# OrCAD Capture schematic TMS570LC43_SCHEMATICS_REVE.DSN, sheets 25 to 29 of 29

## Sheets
25 PAGE15: FET SWs FOR 2nd USB: size B; note: FET SWs FOR USB DEVICE & 2nd HOST
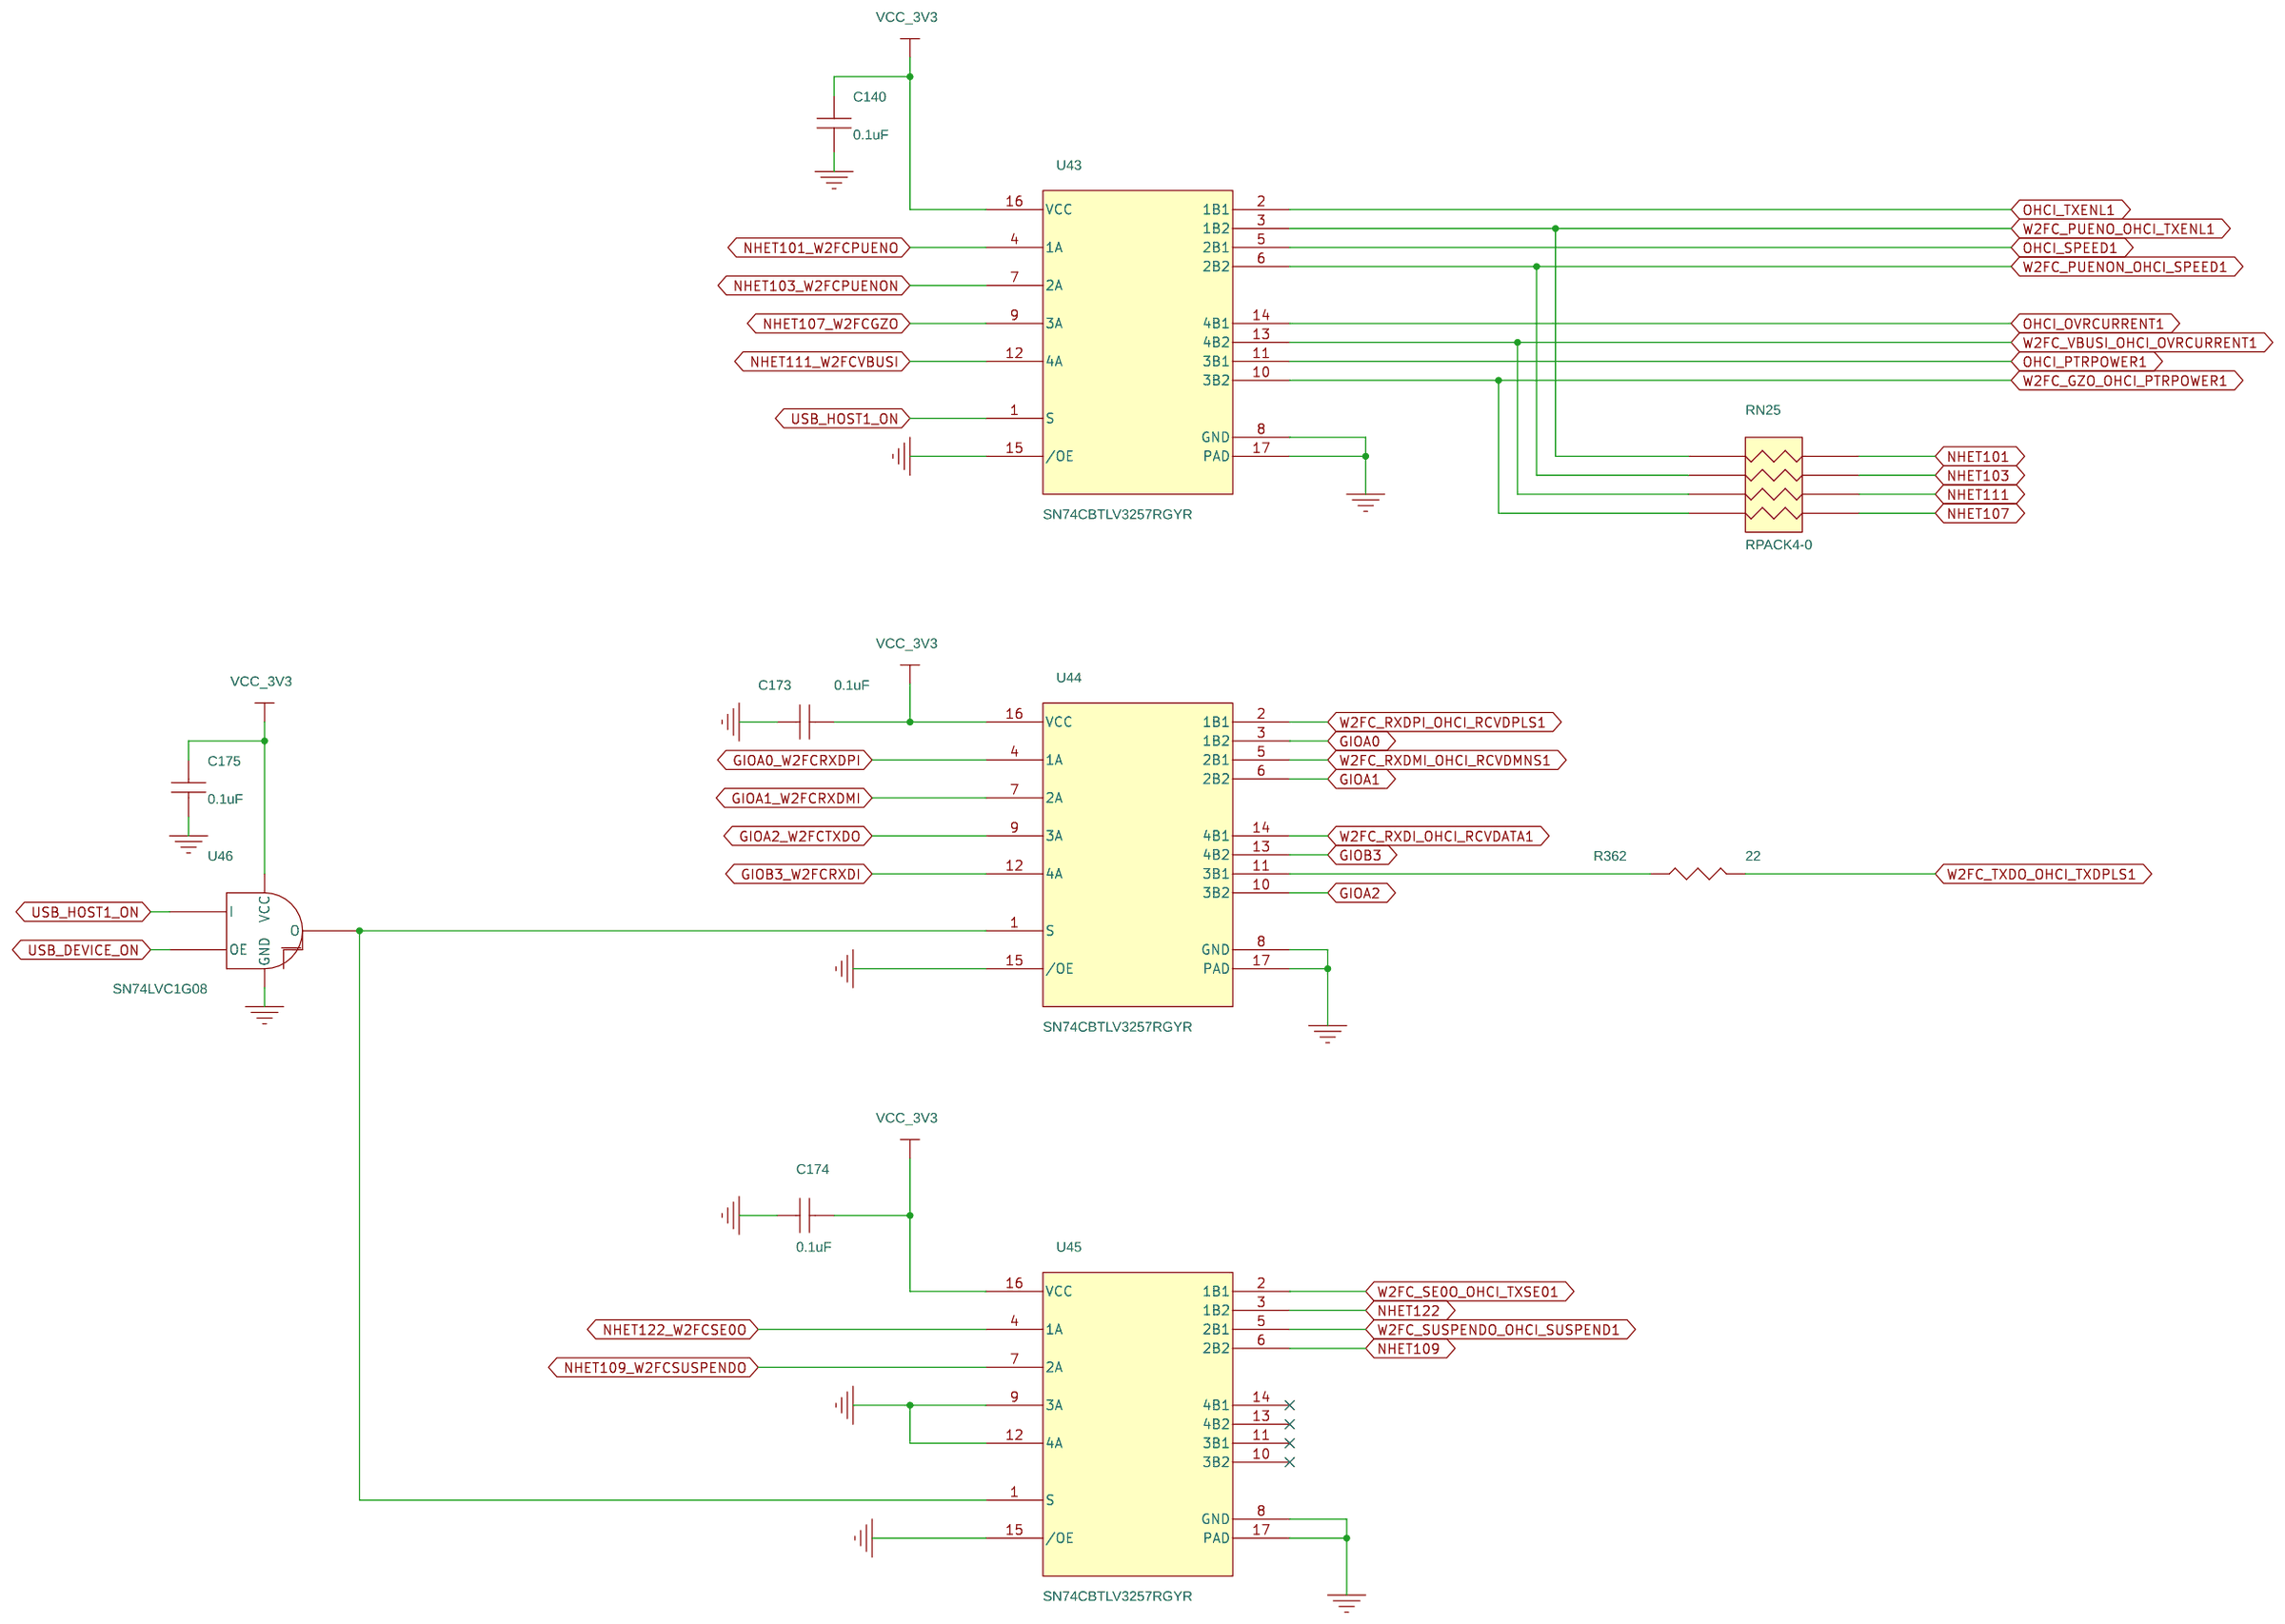
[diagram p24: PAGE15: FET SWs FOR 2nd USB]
26 PAGE06: MCU DCAN, FRAY, LIN: size B; rev: D; note: MCU DCAN, FRAY, LIN
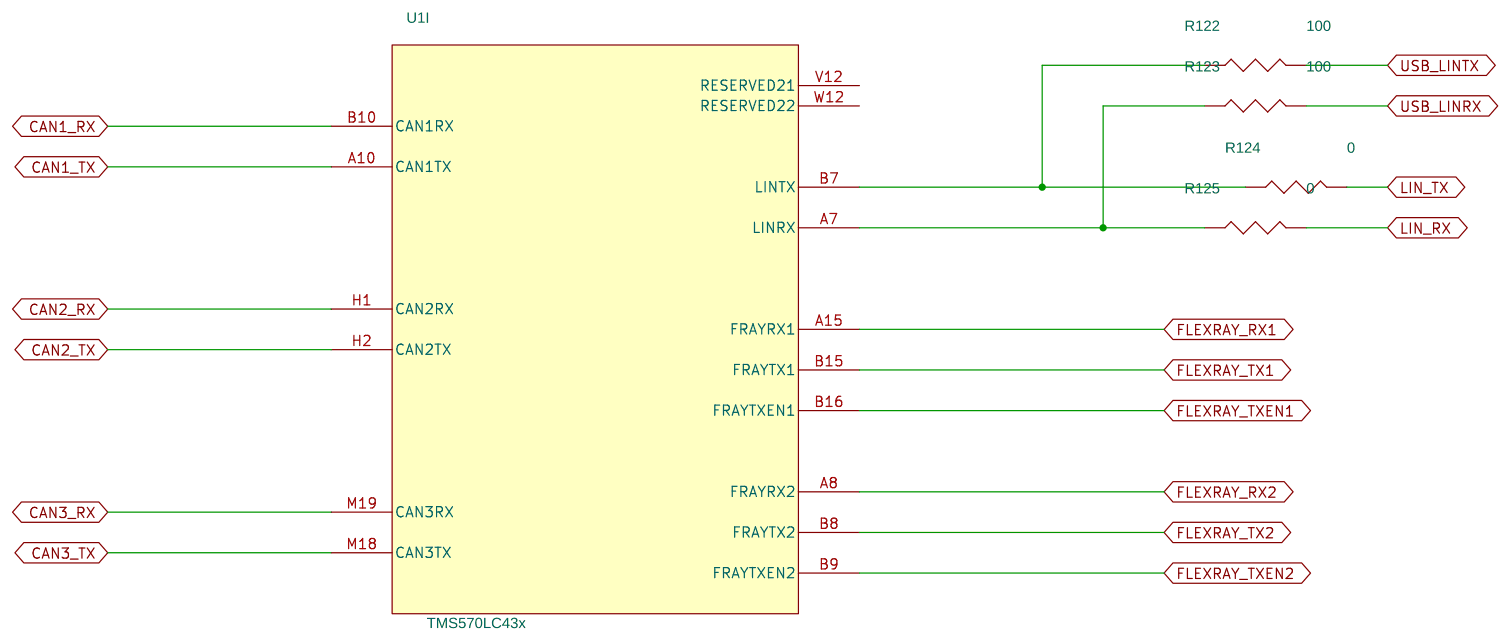
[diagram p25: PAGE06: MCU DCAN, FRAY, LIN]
27 PAGE17: USB Device & 2nd HOST: size B; note: USB Device & 2nd HOST
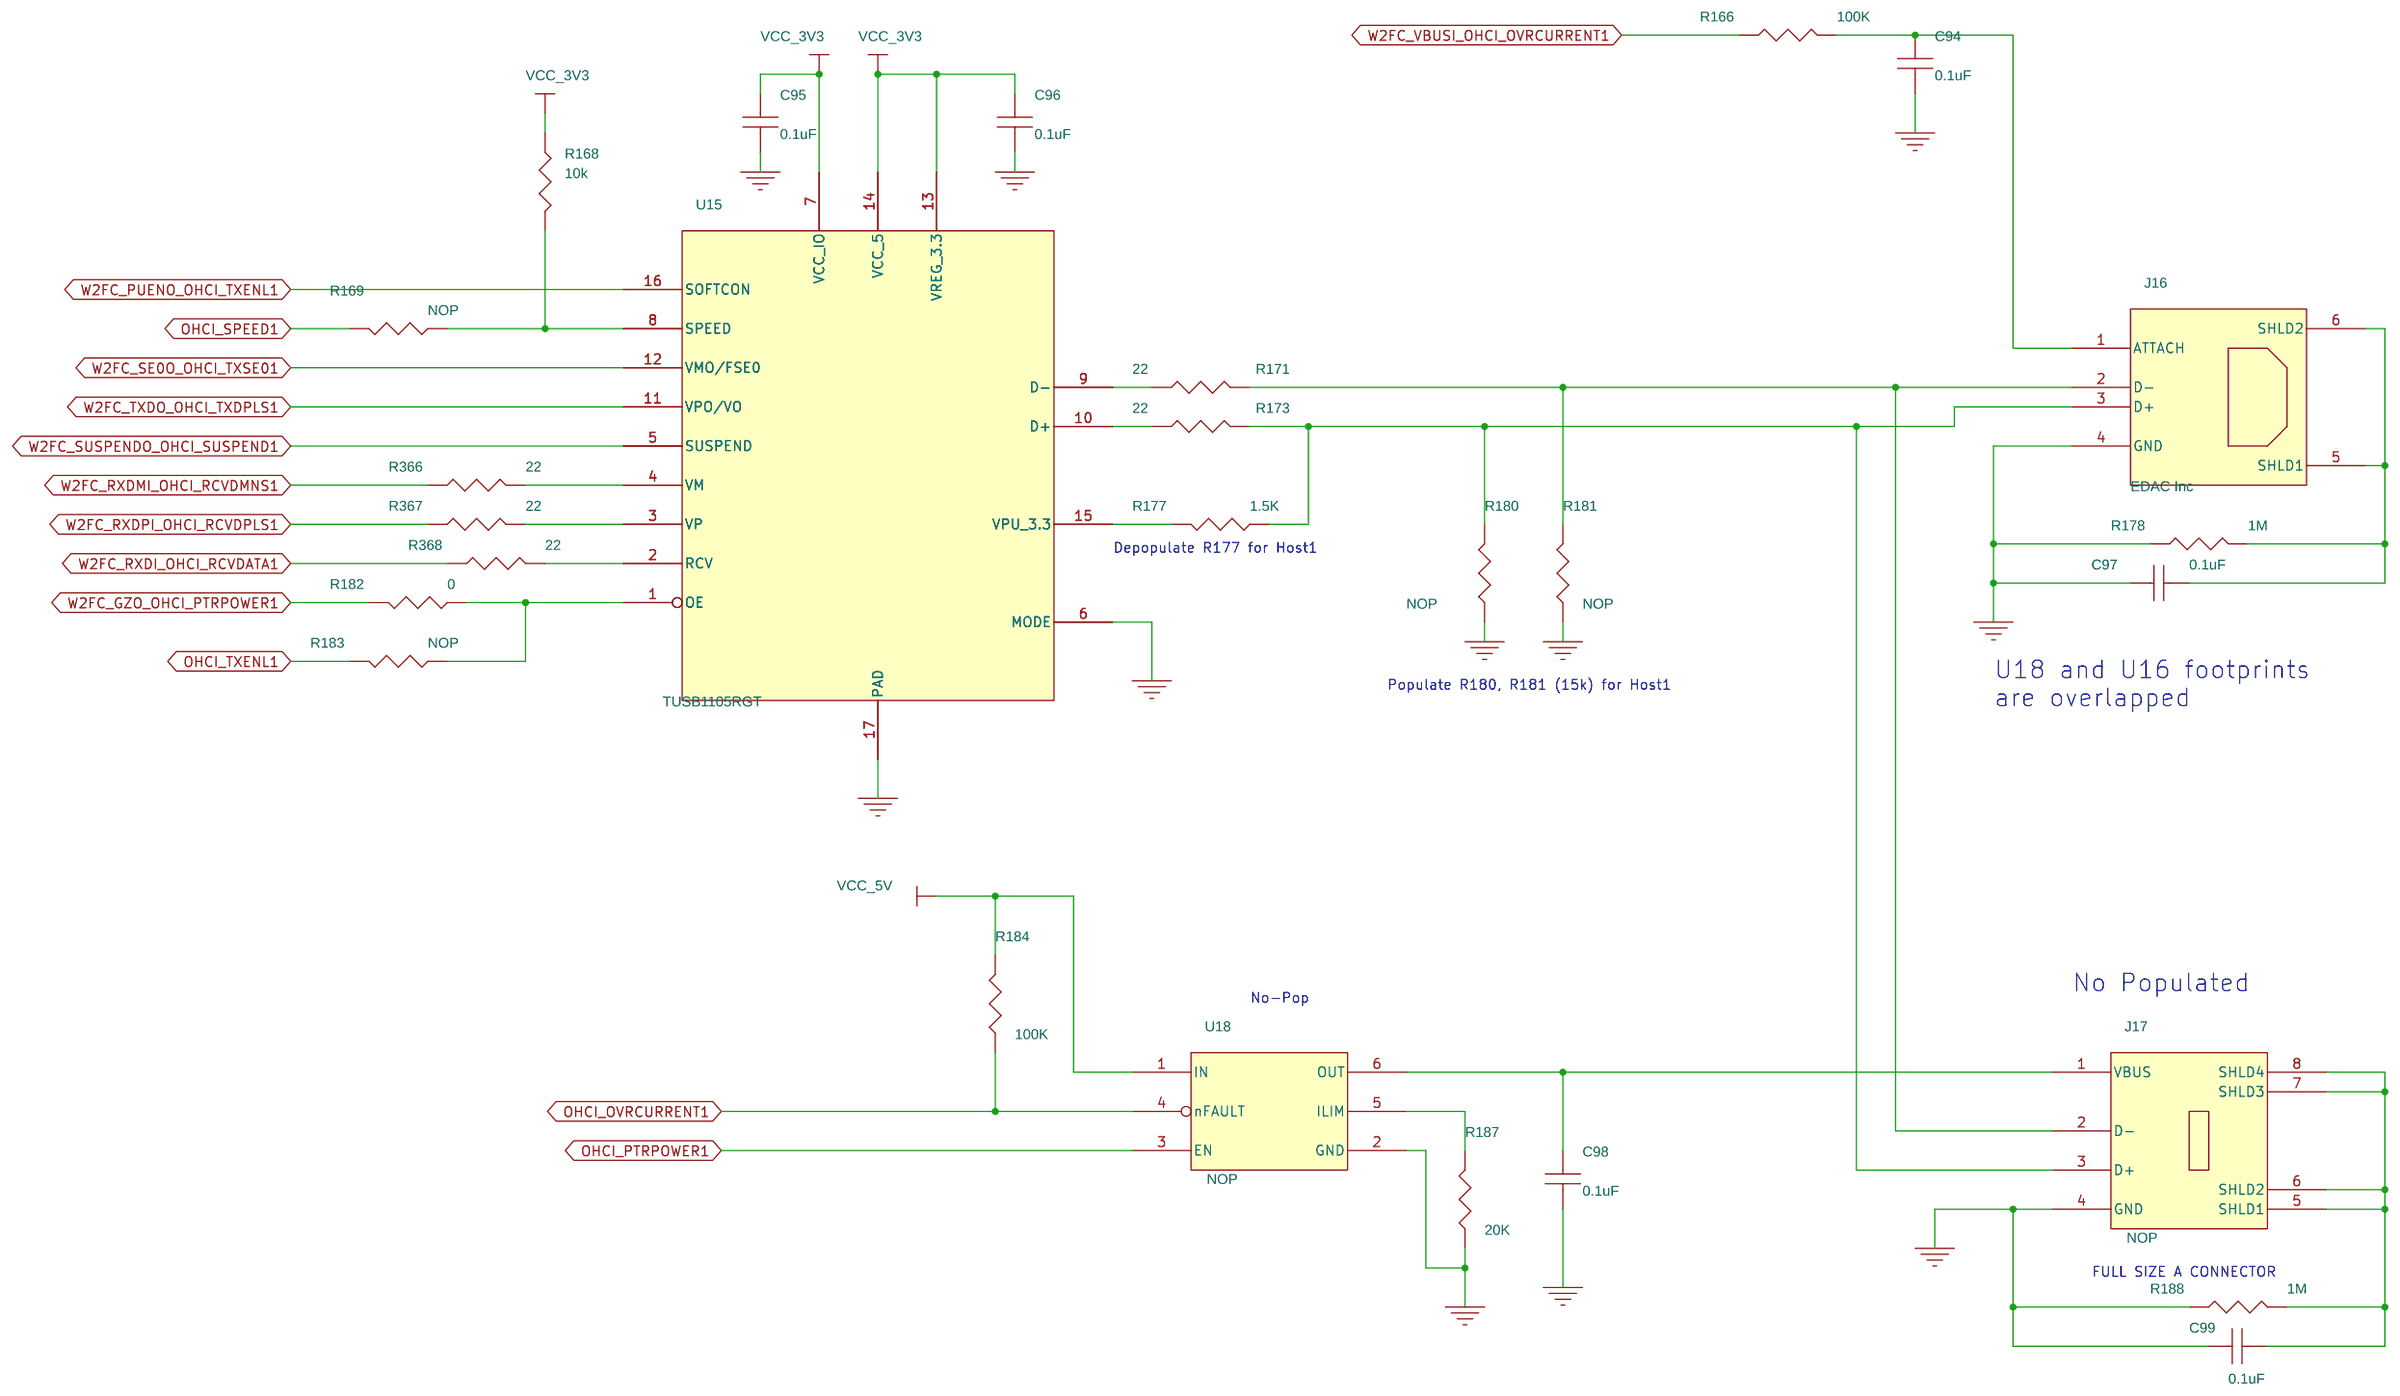
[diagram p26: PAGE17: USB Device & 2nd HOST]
28 PAGE19: Ethernet PHY & Conn: size B; note: Ethernet PHY & Conn
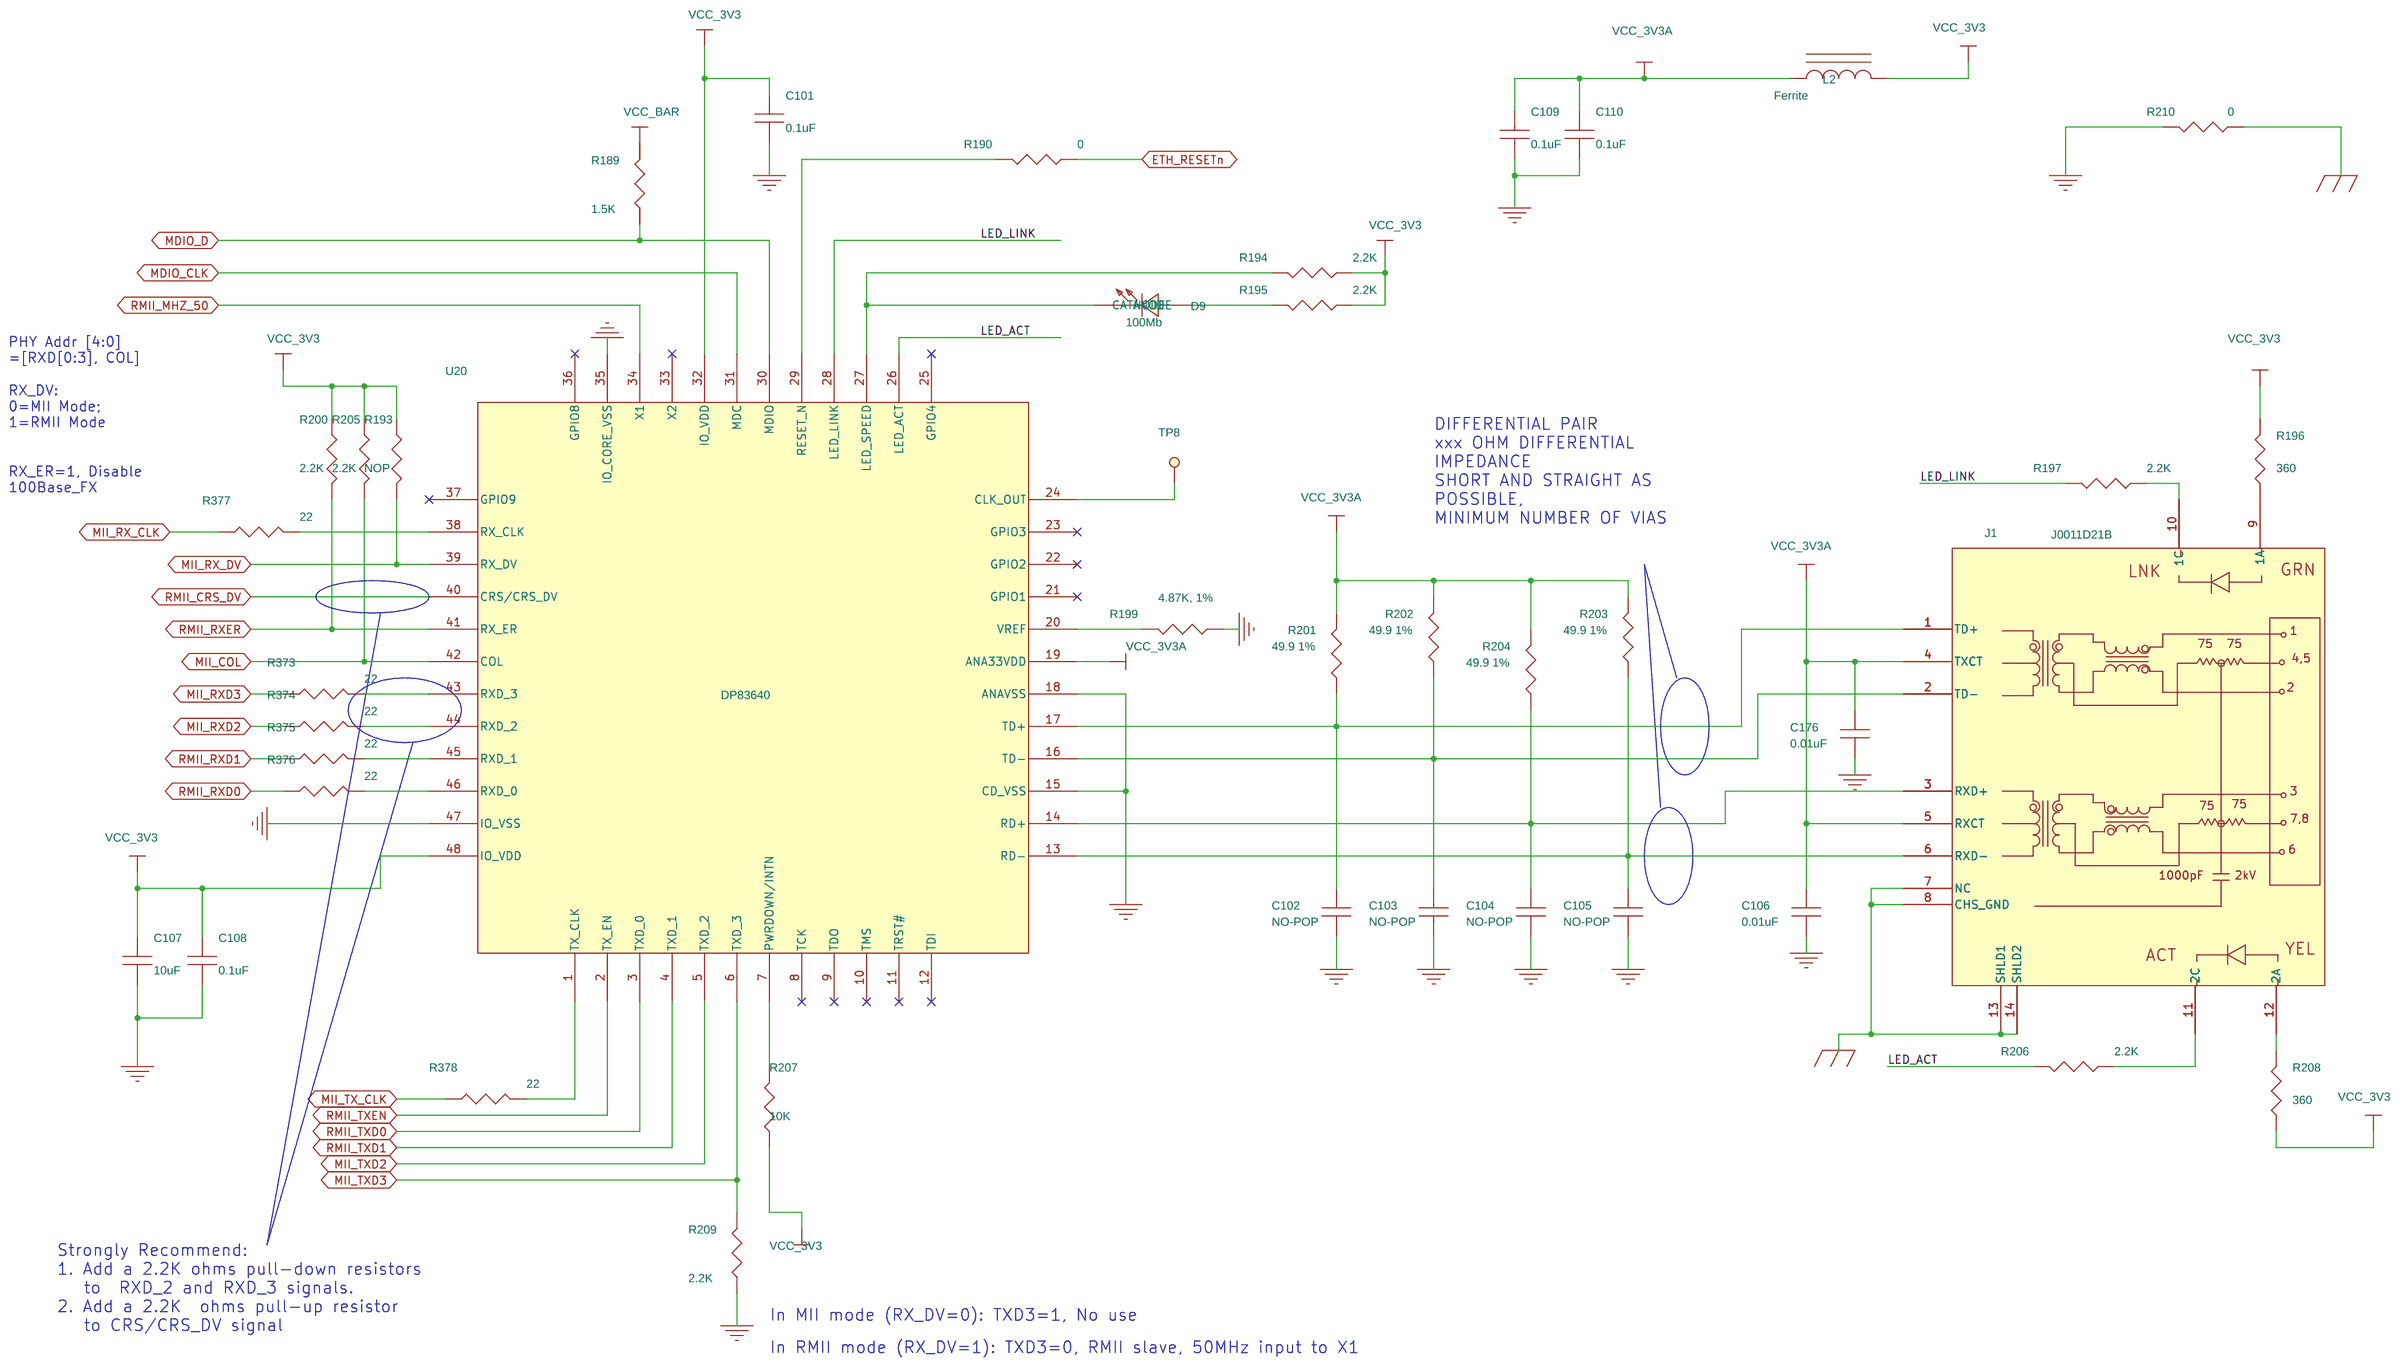
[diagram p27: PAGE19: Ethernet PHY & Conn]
29 PAGE18: FET SW 4 RMII & DIP SW: size B; note: FET SW 4 RMII & DIP SW
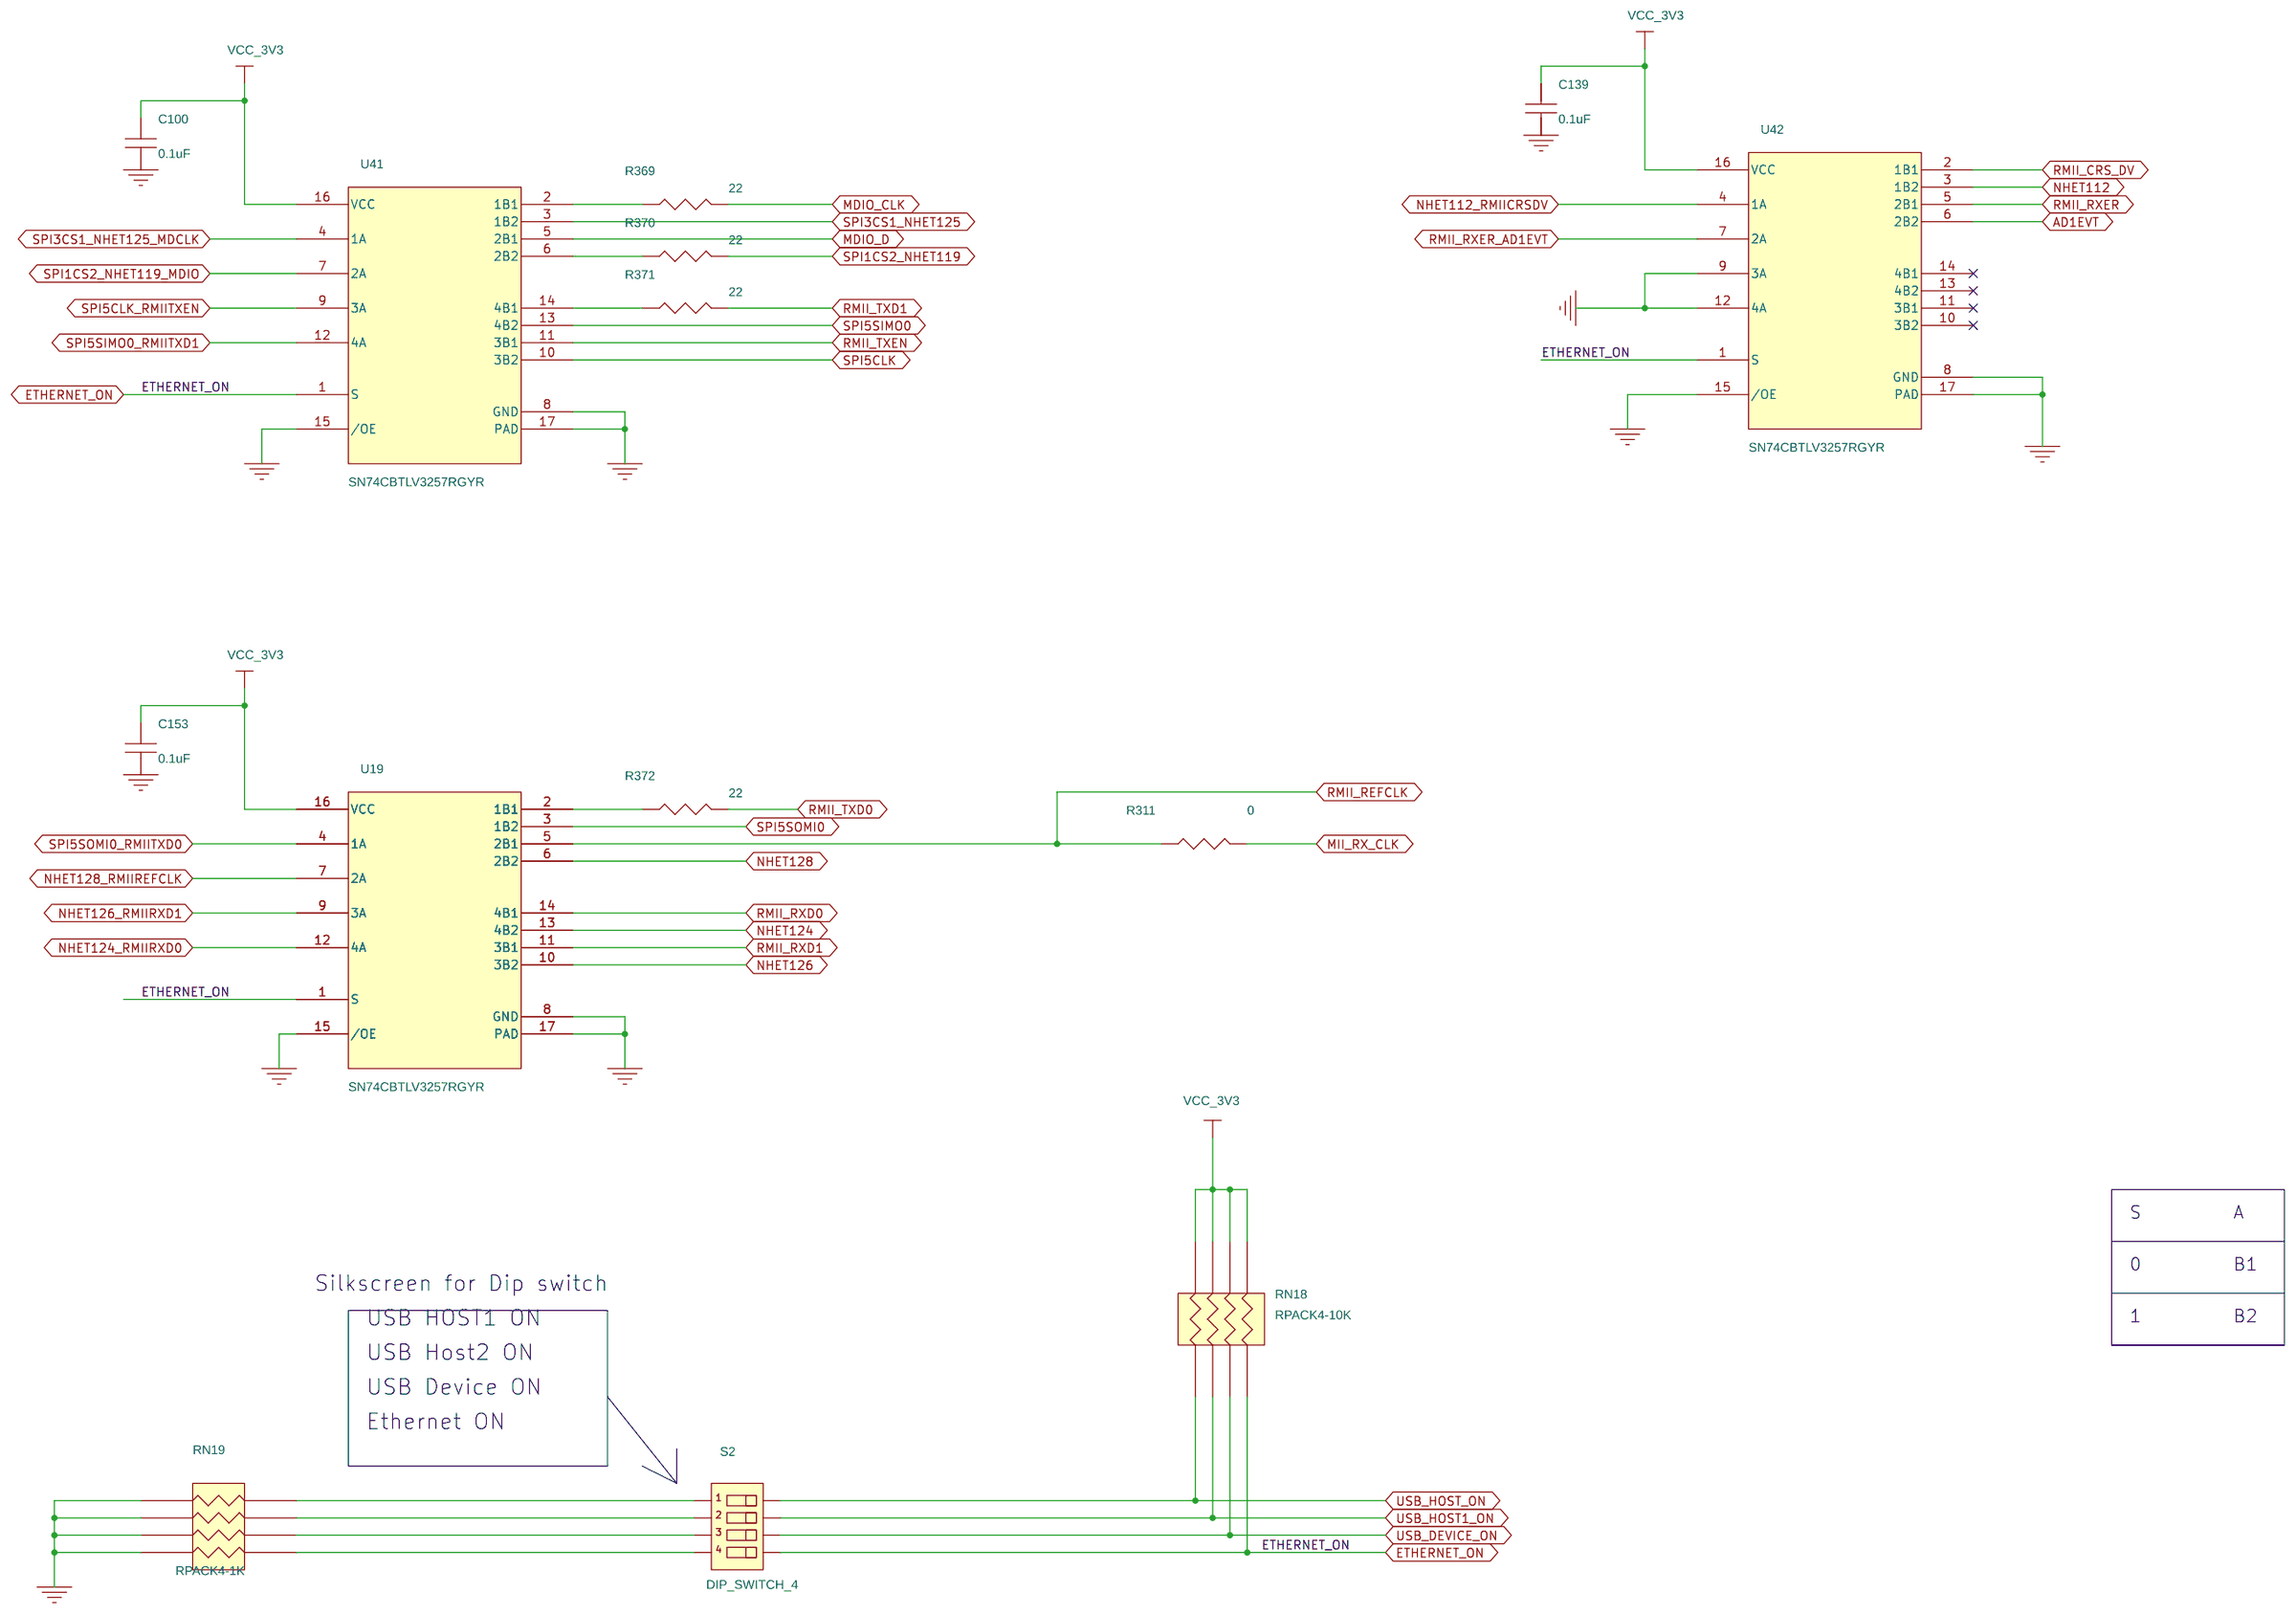
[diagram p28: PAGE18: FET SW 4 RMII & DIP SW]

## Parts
sheet PAGE05: MCU ETM & RSVED_RTP
U1  TMS570LC43x  [BGA337]  (sections A,B,C,D,E,F,G,H,I)
sheet PAGE06: MCU DCAN, FRAY, LIN
R122  100  [r0402]
R123  100  [r0402]
R124  0  [r0402]
R125  0  [r0402]
sheet PAGE15: FET SWs FOR 2nd USB
C140  0.1uF  [c0402]
C173  0.1uF  [c0402]
C174  0.1uF  [c0402]
C175  0.1uF  [c0402]
R362  22  [r0402]
RN25  RPACK4-0  [EXB-28VS]
U43  SN74CBTLV3257RGYR  [VQFN16]
U44  SN74CBTLV3257RGYR  [VQFN16]
U45  SN74CBTLV3257RGYR  [VQFN16]
U46  SN74LVC1G08  [SOT-553]
sheet PAGE17: USB Device & 2nd HOST
C94  0.1uF  [c0402]
C95  0.1uF  [c0402]
C96  0.1uF  [c0402]
C97  0.1uF  [c0402]
C98  0.1uF  [c0402]
C99  0.1uF  [c0402]
J16  EDAC Inc  [USB-B]
J17  NOP  [USB-A]
R166  100K  [r0402]
R168  10k  [r0402]
R169  NOP  [r0402]
R171  22  [r0402]
R173  22  [r0402]
R177  1.5K  [r0402]
R178  1M  [r0402]
R180  NOP  [r0402]
R181  NOP  [r0402]
R182  0  [r0402]
R183  NOP  [r0402]
R184  100K  [r0402]
R187  20K  [r0402]
R188  1M  [r0402]
R366  22  [r0402]
R367  22  [r0402]
R368  22  [r0402]
U15  TUSB1105RGT  [QFN-RGT]
U18  NOP  [SOT-23-6]
sheet PAGE18: FET SW 4 RMII & DIP SW
C100  0.1uF  [c0402]
C139  0.1uF  [c0402]
C153  0.1uF  [c0402]
R311  0  [r0402]
R369  22  [r0402]
R370  22  [r0402]
R371  22  [r0402]
R372  22  [r0402]
RN18  RPACK4-10K  [EXB-28VS]
RN19  RPACK4-1K  [EXB-28VS]
S2  DIP_SWITCH_4  [DIP_SWITCH_4]
U19  SN74CBTLV3257RGYR  [16QFN]
U41  SN74CBTLV3257RGYR  [16QFN]
U42  SN74CBTLV3257RGYR  [16QFN]
sheet PAGE19: Ethernet PHY & Conn
C101  0.1uF  [c0402]
C102  NO-POP  [c0402]
C103  NO-POP  [c0402]
C104  NO-POP  [c0402]
C105  NO-POP  [c0402]
C106  0.01uF  [c0402]
C107  10uF  [c0603]
C108  0.1uF  [c0402]
C109  0.1uF  [c0402]
C110  0.1uF  [c0402]
C176  0.01uF  [c0402]
D9  100Mb  [d0603]
J1  J0011D21B  [rj45-pulse_J0]
L2  Ferrite  [L0805]
R189  1.5K  [r0402]
R190  0  [r0402]
R193  NOP  [r0402]
R194  2.2K  [r0402]
R195  2.2K  [r0402]
R196  360  [r0402]
R197  2.2K  [r0402]
R199  4.87K, 1%  [r0402]
R200  2.2K  [r0402]
R201  49.9 1%  [r0402]
R202  49.9 1%  [r0402]
R203  49.9 1%  [r0402]
R204  49.9 1%  [r0402]
R205  2.2K  [r0402]
R206  2.2K  [r0402]
R207  10K  [r0402]
R208  360  [r0402]
R209  2.2K  [r0402]
R210  0  [r0402]
R373  22  [r0402]
R374  22  [r0402]
R375  22  [r0402]
R376  22  [r0402]
R377  22  [r0402]
R378  22  [r0402]
TP8  TestPoint1  [tp1-6040]
U20  DP83640  [48LQFP]

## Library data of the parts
U1 = TMS570LS30336U_BGA337_19: Manufacturer: TI; PACKAGE: 1; Part Number: TMS570LS3x
R122-R125 = RESISTOR: Manufacturer: Panasonic - ECG; Part Number: ERJ-2GE0R00X
C94-C101 C108-C110 C139 C140 C153 C173-C175 = CAP_NP: Manufacturer: Panasonic - ECG; Part Number: EMK105BJ104KV-F
R171 R173 R362 R366-R378 = R_0: Manufacturer: Panasonic - ECG; Part Number: ERJ-2GEJ220X
RN25 = RPACK4: Manufacturer: Panasonic - ECG; Part Number: EXB-28V220JX
U19 U41-U45 = SN74CBTLV3257RGYR
U46 = SN74LVC1G08: Part Number: SN74LVC1G08DRLR
J16 = USBCONN_B: Part Number: 690-004-621-023
J17 = USBCONN_A: Manufacturer: FCI; Part Number: 73725-0110BLF
R166 = R: Part Number: ERJ-2GEJ104X
R168 R207 = R: Manufacturer: Panasonic - ECG; Part Number: ERJ-2GEJ103X
R169 R182 R183 R190 = R: Manufacturer: Panasonic - ECG; Part Number: ERJ-2GE0R00X
R177 = R_0: Manufacturer: Panasonic - ECG; Part Number: ERJ-2GEJ152X
R178 R188 = R: Manufacturer: Panasonic - ECG; Part Number: ERJ-2GEJ105X
R180 R181 = R_0: Manufacturer: Panasonic - ECG; Part Number: ERJ-2GEJ153X
R184 = R_0: Manufacturer: Panasonic - ECG; Part Number: ERJ-2GEJ104X
R187 = R_0: Manufacturer: Panasonic - ECG; Part Number: ERJ-2GEJ203X
U15 = TUSB1105RGT: Part Number: TUSB1105RGTR
U18 = TPS2552DBV: Manufacturer: TI
R311 = R_0: Part Number: ERJ-2GE0R00X
RN18 = RPACK4: Manufacturer: Panasonic - ECG; Part Number: EXB-28V103JX
RN19 = RPACK4: Manufacturer: Panasonic - ECG; Part Number: EXB-28V102JX
S2 = DIP_SWITCH_4: Manufacturer: C&K Components; Part Number: TDA04-H0-S-B-1-R
C102-C105 = CAP_NP_1: Manufacturer: Panasonic - ECG; Part Number: EMK105BJ104KV-F
C106 C176 = CAP_NP_1: Manufacturer: Panasonic - ECG; Part Number: ECJ-0EB1C103K
C107 = CAP_NP: Manufacturer: Panasonic - ECG; Part Number: JMK107BJ106MA-T
D9 = LED_1: Manufacturer: Panasonic - SSG; Part Number: LNJ926W8CRA
J1 = J0011D01B_0: Manufacturer: Pulse; Part Number: J0011D21BNL
L2 = Ferrite_Bead_0: Manufacturer: Murata Electronics North America; Part Number: BLM21PG221SN1D
R189 = R: Manufacturer: Panasonic - ECG; Part Number: ERJ-2GEJ152X
R193-R195 R197 R200 R205 R206 R209 = R: Manufacturer: Panasonic - ECG; Part Number: ERJ-2RKF2201X
R196 R208 = R: Manufacturer: Panasonic - ECG; Part Number: ERJ-2GEJ361X
R199 = R: Manufacturer: Panasonic - ECG; Part Number: ERJ-2RKF4871X
R201-R204 = R: Manufacturer: Panasonic - ECG; Part Number: ERJ-2RKF49R9X
R210 = R: Part Number: ERJ-2GE0R00X
TP8 = TestPoint1
U20 = DP83640_0: Manufacturer: National Semiconductor; Part Number: DP83640TVV/NOPB

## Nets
GND: C94.2 C95.2 C96.2 C97.1 C98.2 C99.1 C100.2 C101.2 C102.2 C103.2 C104.2 C105.2 C106.2 C107.2 C108.2 C109.2 C110.2 C139.2 C140.2 C153.2 C173.1 C174.1 C175.2 C176.2 J16.4(GND) J17.4(GND) R178.1 R180.2 R181.2 R187.2 R188.1 R199.2 R209.2 R210.2 RN19.1 RN19.2 RN19.3 RN19.4 U15.6(MODE) U15.17(PAD) U18.2(GND) U19.8(GND) U19.15(/OE) U19.17(PAD) U20.15(CD_VSS) U20.18(ANAVSS) U20.35(IO_CORE_VSS) U20.47(IO_VSS) U41.8(GND) U41.15(/OE) U41.17(PAD) U42.8(GND) U42.9(3A) U42.12(4A) U42.15(/OE) U42.17(PAD) U43.8(GND) U43.15(/OE) U43.17(PAD) U44.8(GND) U44.15(/OE) U44.17(PAD) U45.8(GND) U45.9(3A) U45.12(4A) U45.15(/OE) U45.17(PAD) U46.3(GND) ; also on sheet 2 3 5 6 9 10 11 13 14 15 16 17 18 19 22 23 24
GND_EARTH: J1.7(NC) J1.8(CHS_GND) J1.13(SHLD1) J1.14(SHLD2) R210.1
VCC_3V3: C95.1 C96.1 C100.1 C101.1 C107.1 C108.1 C139.1 C140.1 C153.1 C173.2 C174.2 C175.1 L2.2 R168.1 R189.1 R193.2 R194.2 R195.2 R196.1 R200.2 R205.2 R207.2 R208.2 RN18.5 RN18.6 RN18.7 RN18.8 U15.7(VCC_IO) U15.13(VREG_3.3) U15.14(VCC_5) U19.16(VCC) U20.32(IO_VDD) U20.48(IO_VDD) U41.16(VCC) U42.16(VCC) U43.16(VCC) U44.16(VCC) U45.16(VCC) U46.5(VCC) ; also on sheet 3 5 7 8 9 10 13 14 15 16 17 18 19 21
VCC_3V3A: C106.1 C109.1 C110.1 C176.1 J1.4(TXCT) J1.5(RXCT) L2.1 R201.1 R202.1 R203.1 R204.1 U20.19(ANA33VDD)
VCC_5V: R184.1 U18.1(IN) ; also on sheet 10 13 17 19 24
AD1EVT: U42.6(2B2) ; also on sheet 22
CAN1_RX: U1.B10(CAN1RX) ; also on sheet 2 19
CAN1_TX: U1.A10(CAN1TX) ; also on sheet 2 19
CAN2_RX: U1.H1(CAN2RX) ; also on sheet 2 19
CAN2_TX: U1.H2(CAN2TX) ; also on sheet 2 19
CAN3_RX: U1.M19(CAN3RX) ; also on sheet 2
CAN3_TX: U1.M18(CAN3TX) ; also on sheet 2
ETH_RESETn: R190.2 ; also on sheet 5 14 15 22
ETHERNET_ON: RN18.4 S2.5 U19.1(S) U41.1(S) U42.1(S) ; also on sheet 24
FLEXRAY_RX1: U1.A15(FRAYRX1) ; also on sheet 2
FLEXRAY_RX2: U1.A8(FRAYRX2) ; also on sheet 2
FLEXRAY_TX1: U1.B15(FRAYTX1) ; also on sheet 2
FLEXRAY_TX2: U1.B8(FRAYTX2) ; also on sheet 2
FLEXRAY_TXEN1: U1.B16(FRAYTXEN1) ; also on sheet 2
FLEXRAY_TXEN2: U1.B9(FRAYTXEN2) ; also on sheet 2
GIOA0: U44.3(1B2) ; also on sheet 2
GIOA0_W2FCRXDPI: U44.4(1A) ; also on sheet 12
GIOA1: U44.6(2B2) ; also on sheet 2
GIOA1_W2FCRXDMI: U44.7(2A) ; also on sheet 12
GIOA2: U44.10(3B2) ; also on sheet 2
GIOA2_W2FCTXDO: U44.9(3A) ; also on sheet 12
GIOB3: U44.13(4B2) ; also on sheet 2
GIOB3_W2FCRXDI: U44.12(4A) ; also on sheet 12
LED_ACT: R206.1 U20.26(LED_ACT)
LED_LINK: R197.1 U20.28(LED_LINK)
LIN_RX: R125.1 ; also on sheet 2
LIN_TX: R124.1 ; also on sheet 2
MDIO_CLK: R369.2 U20.31(MDC)
MDIO_D: R189.2 U20.30(MDIO) U41.5(2B1)
MII_COL: R205.1 U20.42(COL) ; also on sheet 24
MII_RX_CLK: R311.2 R377.1
MII_RX_DV: R193.1 U20.39(RX_DV) ; also on sheet 24
MII_RXD2: R374.1 ; also on sheet 24
MII_RXD3: R373.1 ; also on sheet 24
MII_TX_CLK: R378.1 ; also on sheet 24
MII_TXD2: U20.5(TXD_2) ; also on sheet 24
MII_TXD3: R209.1 U20.6(TXD_3) ; also on sheet 24
NHET101: RN25.4 ; also on sheet 2
NHET101_W2FCPUENO: U43.4(1A) ; also on sheet 1
NHET103: RN25.3 ; also on sheet 2
NHET103_W2FCPUENON: U43.7(2A) ; also on sheet 1
NHET107: RN25.1 ; also on sheet 2
NHET107_W2FCGZO: U43.9(3A) ; also on sheet 1
NHET109: U45.6(2B2) ; also on sheet 2
NHET109_W2FCSUSPENDO: U45.7(2A) ; also on sheet 1
NHET111: RN25.2 ; also on sheet 2
NHET111_W2FCVBUSI: U43.12(4A) ; also on sheet 1
NHET112: U42.3(1B2) ; also on sheet 2
NHET112_RMIICRSDV: U42.4(1A) ; also on sheet 1
NHET122: U45.3(1B2) ; also on sheet 2
NHET122_W2FCSE0O: U45.4(1A) ; also on sheet 1
NHET124: U19.13(4B2) ; also on sheet 2
NHET124_RMIIRXD0: U19.12(4A) ; also on sheet 1
NHET126: U19.10(3B2) ; also on sheet 2
NHET126_RMIIRXD1: U19.9(3A) ; also on sheet 1
NHET128: U19.6(2B2) ; also on sheet 2
NHET128_RMIIREFCLK: U19.7(2A) ; also on sheet 1
OHCI_OVRCURRENT1: R184.2 U18.4(nFAULT) U43.14(4B1)
OHCI_PTRPOWER1: U18.3(EN) U43.11(3B1)
OHCI_SPEED1: R169.2 U43.5(2B1)
OHCI_TXENL1: R183.2 U43.2(1B1)
RMII_CRS_DV: U20.40(CRS/CRS_DV) U42.2(1B1)
RMII_MHZ_50: U20.34(X1) ; also on sheet 14
RMII_REFCLK: R311.1 U19.5(2B1) ; also on sheet 14
RMII_RXD0: R376.1 U19.14(4B1)
RMII_RXD1: R375.1 U19.11(3B1)
RMII_RXER: R200.1 U20.41(RX_ER) U42.5(2B1)
RMII_RXER_AD1EVT: U42.7(2A) ; also on sheet 6
RMII_TXD0: R372.2 U20.3(TXD_0)
RMII_TXD1: R371.2 U20.4(TXD_1)
RMII_TXEN: U20.2(TX_EN) U41.11(3B1)
SPI1CS2_NHET119: R370.2 ; also on sheet 22
SPI1CS2_NHET119_MDIO: U41.7(2A) ; also on sheet 7
SPI3CS1_NHET125: U41.3(1B2) ; also on sheet 2
SPI3CS1_NHET125_MDCLK: U41.4(1A) ; also on sheet 7
SPI5CLK: U41.10(3B2) ; also on sheet 22
SPI5CLK_RMIITXEN: U41.9(3A) ; also on sheet 7
SPI5SIMO0: U41.13(4B2) ; also on sheet 22
SPI5SIMO0_RMIITXD1: U41.12(4A) ; also on sheet 7
SPI5SOMI0: U19.3(1B2) ; also on sheet 22
SPI5SOMI0_RMIITXD0: U19.4(1A) ; also on sheet 7
USB_DEVICE_ON: RN18.3 S2.6 U46.1(OE)
USB_HOST1_ON: RN18.2 S2.7 U43.1(S) U46.2(I)
USB_HOST_ON: RN18.1 S2.8 ; also on sheet 24
USB_LINRX: R123.1 ; also on sheet 23
USB_LINTX: R122.1 ; also on sheet 23
W2FC_GZO_OHCI_PTRPOWER1: R182.2 RN25.8 U43.10(3B2)
W2FC_PUENO_OHCI_TXENL1: RN25.5 U15.16(SOFTCON) U43.3(1B2)
W2FC_PUENON_OHCI_SPEED1: RN25.6 U43.6(2B2)
W2FC_RXDI_OHCI_RCVDATA1: R368.1 U44.14(4B1)
W2FC_RXDMI_OHCI_RCVDMNS1: R366.1 U44.5(2B1)
W2FC_RXDPI_OHCI_RCVDPLS1: R367.1 U44.2(1B1)
W2FC_SE0O_OHCI_TXSE01: U15.12(VMO/FSE0) U45.2(1B1)
W2FC_SUSPENDO_OHCI_SUSPEND1: U15.5(SUSPEND) U45.5(2B1)
W2FC_TXDO_OHCI_TXDPLS1: R362.2 U15.11(VPO/VO)
W2FC_VBUSI_OHCI_OVRCURRENT1: R166.1 RN25.7 U43.13(4B2)
N16387121: C102.1 J1.1(TD+) R201.2 U20.17(TD+)
N16387145: R190.1 U20.29(RESET_N)
N16387227: D9.2(CATHODE) R194.1 U20.27(LED_SPEED)
N16387303: D9.1(ANODE) R195.1
N16387603: C104.1 J1.3(RXD+) R204.2 U20.14(RD+)
N16387611: C103.1 J1.2(TD-) R202.2 U20.16(TD-)
N16387623: C105.1 J1.6(RXD-) R203.2 U20.13(RD-)
N16387725: J1.11(2C) R206.2
N16387761: R199.1 U20.20(VREF)
N16387911: TP8.1 U20.24(CLK_OUT)
N16388051: J1.10(1C) R197.2
N17059795: RN19.5 S2.4
N17059817: RN19.6 S2.3
N17059819: RN19.7 S2.2
N17059821: RN19.8 S2.1
N17219643: R207.1 U20.7(PWRDOWN/INTN)
N17372778: R122.2 R124.2 U1.B7(LINTX)
N17372787: R123.2 R125.2 U1.A7(LINRX)
N17382123: C97.2 J16.5(SHLD1) J16.6(SHLD2) R178.2
N17382225: R182.1 R183.1 U15.1(OE)
N17382253: J16.2(D-) J17.2(D-) R171.1 R181.1
N17382255: J16.3(D+) J17.3(D+) R173.1 R177.2 R180.1
N17382291: R168.2 R169.1 U15.8(SPEED)
N17382365: R171.2 U15.9(D-)
N17382367: R173.2 U15.10(D+)
N17382395: R177.1 U15.15(VPU_3.3)
N17382455: C98.1 J17.1(VBUS) U18.6(OUT)
N17382473: R187.1 U18.5(ILIM)
N17382585: C94.1 J16.1(ATTACH) R166.2
N17382627: C99.2 J17.5(SHLD1) J17.6(SHLD2) J17.7(SHLD3) J17.8(SHLD4) R188.2
N17770384: J1.12(2A) R208.1
N18120766: R378.2 U20.1(TX_CLK)
N18239450: U44.1(S) U45.1(S) U46.4(O)
N18278813: R362.1 U44.11(3B1)
N18279060: R366.2 U15.4(VM)
N18279063: R367.2 U15.3(VP)
N18279066: R368.2 U15.2(RCV)
N18279097: R369.1 U41.2(1B1)
N18279118: R370.1 U41.6(2B2)
N18279139: R371.1 U41.14(4B1)
N18279161: R372.1 U19.2(1B1)
N18279224: R373.2 U20.43(RXD_3)
N18279227: R374.2 U20.44(RXD_2)
N18279230: R375.2 U20.45(RXD_1)
N18279233: R376.2 U20.46(RXD_0)
N18279461: R377.2 U20.38(RX_CLK)
N18733179: J1.9(1A) R196.2

Not connected (* = marked no-connect by the designer): U1 V12(RESERVED21) W12(RESERVED22); U20 8(TCK)* 9(TDO)* 10(TMS)* 11(TRST#)* 12(TDI)* 21(GPIO1)* 22(GPIO2)* 23(GPIO3)* 25(GPIO4)* 33(X2)* 36(GPIO8)* 37(GPIO9)*; U42 10(3B2)* 11(3B1)* 13(4B2)* 14(4B1)*; U45 10(3B2)* 11(3B1)* 13(4B2)* 14(4B1)*

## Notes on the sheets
sheet 27
- Depopulate R177 for Host1
- U18 and U16 footprints
  are overlapped
- Populate R180, R181 (15k) for Host1
- No Populated
- No-Pop
- FULL SIZE A CONNECTOR
sheet 28
- PHY Addr [4:0]
  =[RXD[0:3], COL]
- RX_DV:
  0=MII Mode;
  1=RMII Mode
- DIFFERENTIAL PAIR
  xxx OHM DIFFERENTIAL
  IMPEDANCE
  SHORT AND STRAIGHT AS
  POSSIBLE,
  MINIMUM NUMBER OF VIAS
- RX_ER=1, Disable
  100Base_FX
- Strongly Recommend:
  1. Add a 2.2K ohms pull-down resistors
     to  RXD_2 and RXD_3 signals.
  2. Add a 2.2K  ohms pull-up resistor
     to CRS/CRS_DV signal
- In MII mode (RX_DV=0): TXD3=1, No use
- In RMII mode (RX_DV=1): TXD3=0, RMII slave, 50MHz input to X1
sheet 29
- S
- A
- 0
- B1
- Silkscreen for Dip switch
- USB HOST1 ON
- 1
- B2
- USB Host2 ON
- USB Device ON
- Ethernet ON
